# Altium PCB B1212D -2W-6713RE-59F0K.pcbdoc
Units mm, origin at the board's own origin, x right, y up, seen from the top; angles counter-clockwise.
Board outline 42 x 16 mm, 2 copper layers (Top Layer, Bottom Layer), stack 1.58 mm thick; 16 components, 10 nets, 42 pads, 75 vias.
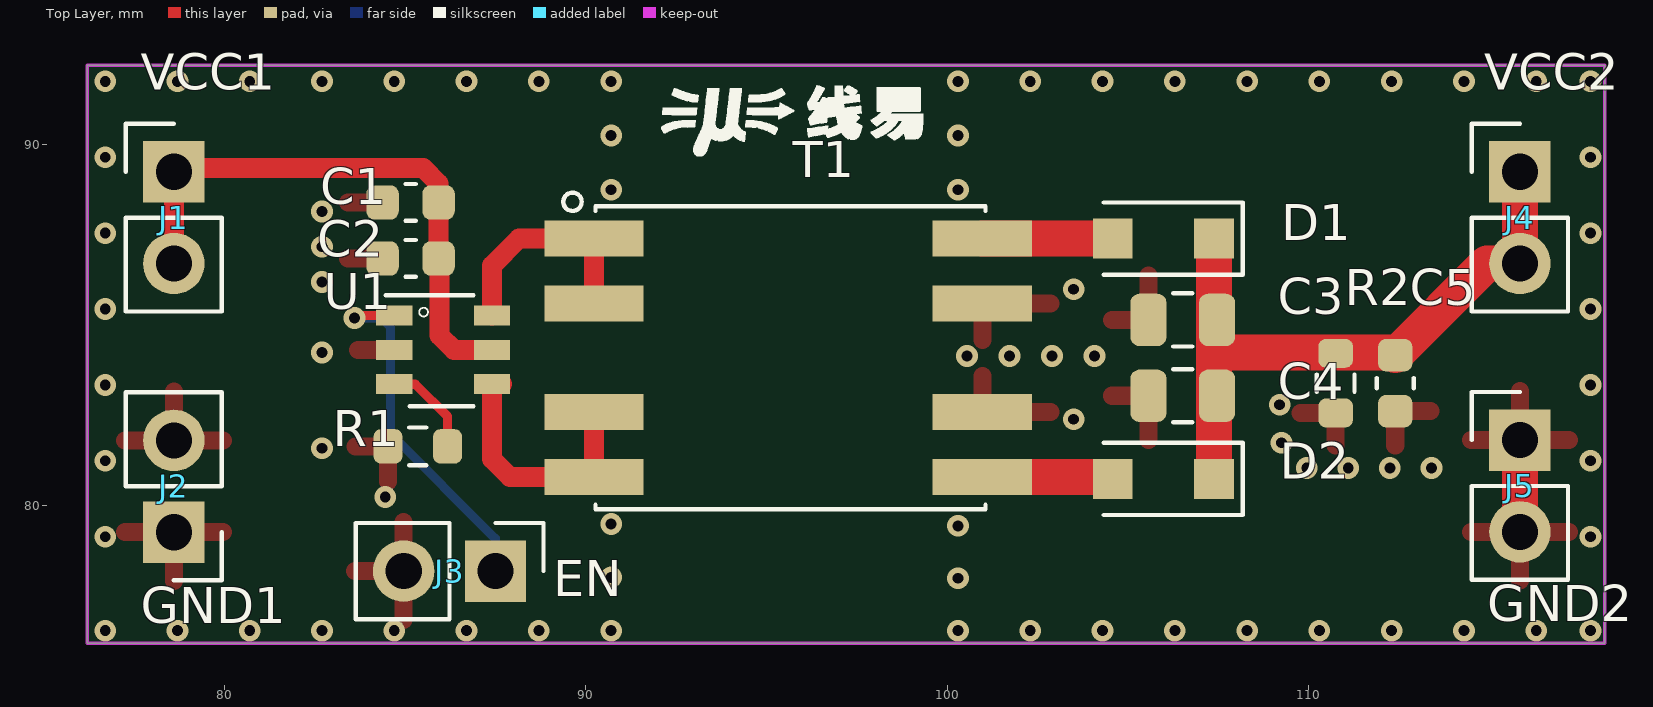
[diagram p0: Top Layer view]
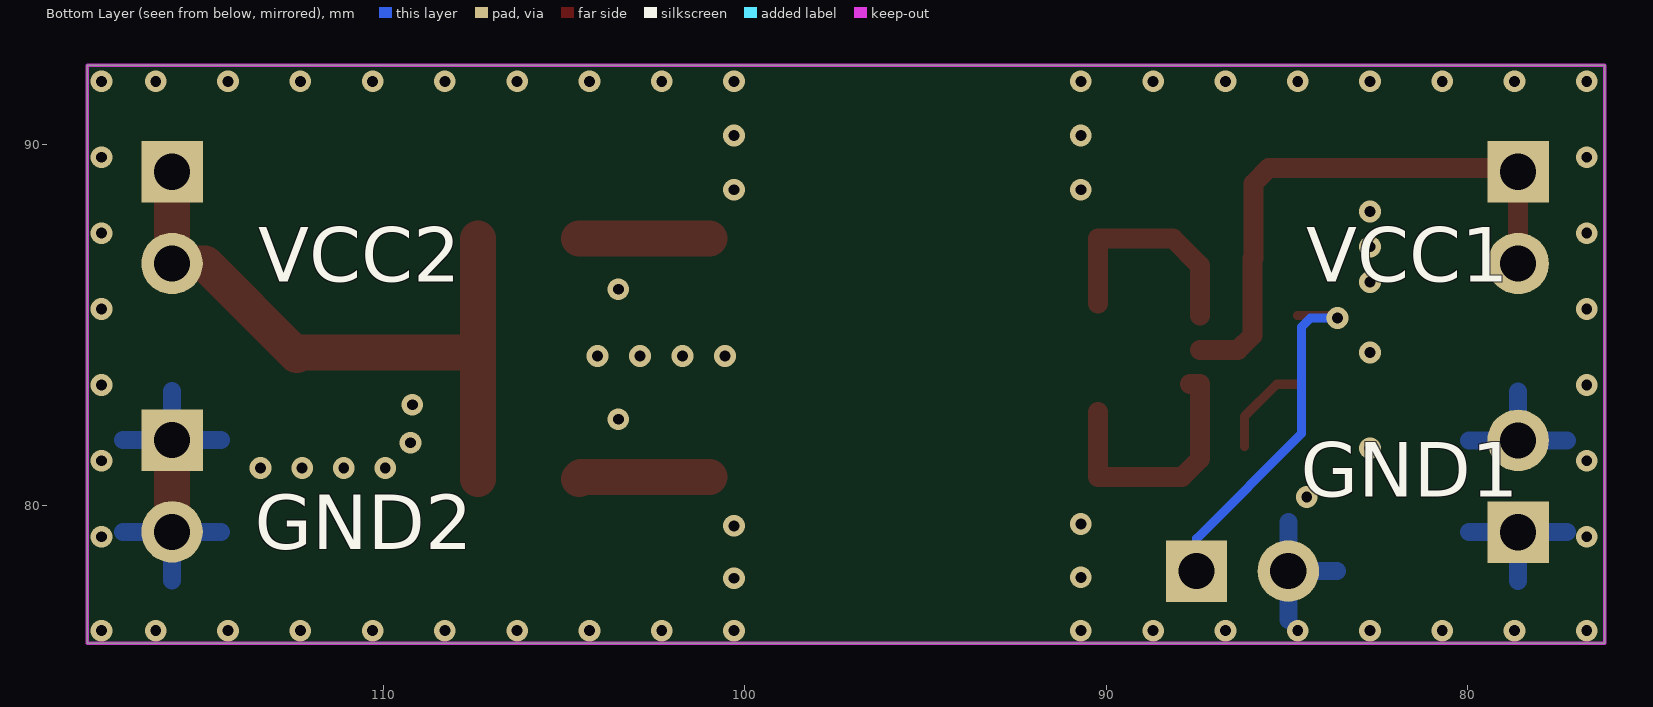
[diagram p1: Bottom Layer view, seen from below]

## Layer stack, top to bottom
Top Solder Mask Layer: solder mask 0.01, Dk 3.3
Top Layer: signal copper 0.035
Dielectric2: surface 1.51, FR4, Dk 4.5
Bottom Layer: signal copper 0.035
Bottom Solder Mask Layer: solder mask 0.01, Dk 3.3

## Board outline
76.2,92.2 118.2,92.2 118.2,76.2 76.2,76.2

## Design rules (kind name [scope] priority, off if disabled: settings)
BoardOutlineClearance copperThickness1oz [All] p0: genericclearance=0.254 ignorepadtopadclearanceinfootprint=FALSE except(0: Arc-SplitContinuation Track-SplitContinuation SMDPad-SplitContinuation THPad-SplitContinuation Via-SplitContinuation Fill-SplitContinuation Poly-SplitContinuation Region-SplitContinuation Text-SplitContinuation)
BoardOutlineClearance otherClearance [All] p0: genericclearance=0.254 ignorepadtopadclearanceinfootprint=FALSE except(0: Arc-SplitContinuation Track-SplitContinuation SMDPad-SplitContinuation THPad-SplitContinuation Via-SplitContinuation Fill-SplitContinuation Poly-SplitContinuation Region-SplitContinuation Text-SplitContinuation)
Clearance copperThickness1oz [All] p1: gap=0.178 ignorepadtopadclearanceinfootprint=FALSE
Clearance otherClearance [All] p1: gap=0.178 ignorepadtopadclearanceinfootprint=FALSE
DiffPairsRouting differentialPair [All] p1: maxuncoupledlength=10 minlimit=5 maxlimit=Infinity mostfreqgap=6 toplayer_minwidth=5 toplayer_prefwidth=100 toplayer_maxwidth=100 bottomlayer_minwidth=5 bottomlayer_prefwidth=100 bottomlayer_maxwidth=100
PasteMaskExpansion pasteMaskExpansion [All] p1: expansion=0
PlaneConnect innerPlane [All] p1: planeconnectstyle=Relief reliefexpansion=0.508 reliefentries=4 reliefconductorwidth=0.254 reliefairgap=0.254
PolygonConnect copper0 [All] p1: connectstyle=Relief reliefentries=4 reliefconductorwidth=19.685 polygonreliefangle="90 Angle" airgapwidth=19.685
RoutingVias viaSize [All] p1: viastyle="Through Hole" holewidth=24 minholewidth=11.811 maxholewidth=393.7 width=24 minwidth=11.811 maxwidth=393.7
SolderMaskExpansion solderMaskExpansion [IsVia] p1: useseparateexpansions=TRUE expansion=-1000 expansionbottom=-1000
SolderMaskExpansion solderMaskExpansion [All] p2: useseparateexpansions=TRUE expansion=2 expansionbottom=2
Width copperThickness1oz [All] p1: maxlimit=100 minlimit=5 preferedwidth=10

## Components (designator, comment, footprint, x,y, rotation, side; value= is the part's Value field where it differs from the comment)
C1 "10uF" C0603#1 85.15,88.4 r0 top
C2 "100nF" C0603#1 85.15,86.85 r0 top
C3 "10uF" C0603#2 106.518,85.15 r0 top
C4 "NC" coileasy:C_0805 106.518,83.05 r0 top
C5 "100nF" C0603#1 112.4,83.4 r90 top
D1 "B5819WS" SOD-323_L1.8-W1.3-LS2.5-RD 105.883,87.45 r180 top
D2 "B5819WS" SOD-323_L1.8-W1.3-LS2.5-RD 105.883,80.8 r180 top
J1 "HX PZ2.54-1x2P ZZ" HDR-TH_2P-P2.54-V-M-3 78.6,89.25 r0 top
J2 "HX PZ2.54-1x2P ZZ" HDR-TH_2P-P2.54-V-M-3 78.6,79.275 r180 top
J3 "HX PZ2.54-1x2P ZZ" HDR-TH_2P-P2.54-V-M-3 87.5,78.2 r270 top
J4 "HX PZ2.54-1x2P ZZ" HDR-TH_2P-P2.54-V-M-3 115.85,89.25 r0 top
J5 "HX PZ2.54-1x2P ZZ" HDR-TH_2P-P2.54-V-M-3 115.85,81.825 r0 top
R1 "R" coileasy:R_0603 85.35,81.65 r180 top
R2 "10kΩ" R0603 110.75,83.4 r270 top
T1 "CMT59F0K" "My Library:CMT59F0K" 95.6,84.1 r0 top
U1 "CMP6713RE" "My Library:SOT-23-6" 85.892,84.35 r0 top

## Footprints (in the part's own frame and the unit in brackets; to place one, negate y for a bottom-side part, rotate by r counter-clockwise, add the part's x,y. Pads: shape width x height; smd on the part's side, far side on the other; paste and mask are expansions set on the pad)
C0603#1 [mm]
  rrect50% 0.9x0.95 smd paste+0 mask+0: 1(-0.775,0) 2(0.775,0)
  silkscreen extent -0.14,-0.51 0.14,0.51
C0603#2 [mm]
  rrect50% 1x1.45 smd paste+0 mask+0: 1(-0.95,0) 2(0.95,0)
  silkscreen extent -0.26,-0.73 0.26,0.73
coileasy:C_0805 [mm]
  rrect50% 1x1.45 smd paste+0 mask+0: 1(-0.95,0) 2(0.95,0)
  silkscreen extent -0.26,-0.73 0.26,0.73
coileasy:R_0603 [mm]
  rrect50% 0.8x0.95 smd paste+0 mask+0: 1(-0.825,0) 2(0.825,0)
  silkscreen extent -0.24,-0.52 0.24,0.52
HDR-TH_2P-P2.54-V-M-3 [mm]
  rect 1.7x1.7 hole 1 paste+0 mask+0: 1(0,0)
  round 1.7 hole 1 paste+0 mask+0: 2(0,-2.54)
  silkscreen extent -1.33,-3.87 1.33,1.33
"My Library:CMT59F0K" [mm]
  rect 2.75x1 smd paste+0 mask+0: 1(-5.375,3.3) 2(-5.375,1.5) 3(-5.375,-1.5) 4(-5.375,-3.3) 5(5.375,-3.3) 6(5.375,-1.5) 7(5.375,1.5) 8(5.375,3.3)
  silkscreen extent -6.22,-4.19 5.46,4.57
"My Library:SOT-23-6" [mm]
  rect 1x0.55 smd paste+0 mask+0: 1(-1.192,0.921) 2(-1.192,-0.029) 3(-1.192,-0.979) 4(1.508,-0.979) 5(1.508,-0.029) 6(1.508,0.921)
  silkscreen extent -1.43,-1.59 1,1.48
R0603 [mm]
  rrect50% 0.8x0.95 smd paste+0 mask+0: 1(-0.825,0) 2(0.825,0)
  silkscreen extent -0.24,-0.52 0.24,0.52
SOD-323_L1.8-W1.3-LS2.5-RD [mm]
  rect 1.1x1.1 smd paste+0 mask+0: 1(-1.5,0.05) 2(1.3,0.05)
  silkscreen extent -2.3,-0.95 1.55,1.05

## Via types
v1: diameter 0.6, hole 0.3, Top Layer to Bottom Layer, 75 vias

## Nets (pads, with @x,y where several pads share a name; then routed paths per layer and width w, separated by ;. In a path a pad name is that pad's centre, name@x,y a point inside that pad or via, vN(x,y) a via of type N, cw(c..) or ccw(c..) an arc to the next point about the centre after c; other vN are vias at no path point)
$1N7: J3.1 U1.1 | length 10.3
  Top Layer w0.25: U1.1 83.721,85.271 v1@83.65,85.2 ; v1@83.65,85.2 v1(83.6,85.2) 83.6,85.15 v1@83.65,85.2
  Bottom Layer w0.25: v1(83.6,85.2) 84.35,85.2 84.6,84.95 84.6,82 87.5,79.1 J3.1
$1N10: R1.1 U1.3 | length 2.7
  Top Layer w0.254: U1.3 85.279,83.371 86.175,82.475 R1.1
D1: D1.2 T1.8 | length 3.6
  Top Layer w1: T1.8 D1.2
D2: D2.2 T1.5 | length 3.6
  Top Layer w1: T1.5 104.533,80.8 D2.2
GND1: C1.1 C2.1 J2.1 J2.2 J3.2 R1.2 U1.2
  other v1: 76.7,76.55 78.7,76.55 80.7,76.55 82.7,76.55 84.7,76.55 86.7,76.55 88.7,76.55 90.7,76.55 90.7,78.025 76.7,79.15 90.7,79.5 84.45,80.25 76.7,81.25 82.7,81.6 76.7,83.35 82.7,84.25 76.7,85.45 82.7,86.2 82.7,87.175 76.7,87.55 82.7,88.15 90.7,88.75 76.7,89.65 90.7,90.25 76.7,91.75 78.7,91.75 80.7,91.75 82.7,91.75 84.7,91.75 86.7,91.75 88.7,91.75 90.7,91.75
GND2: C3.1 C4.1 C5.1 J5.1 J5.2 R2.2 T1.6 T1.7 | length 2.5
  Top Layer w1: J5.2 J5.1
  other v1: 100.3,76.55 102.3,76.55 104.3,76.55 106.3,76.55 108.3,76.55 110.3,76.55 112.3,76.55 114.3,76.55 116.3,76.55 117.8,76.55 100.3,78 117.8,79.15 100.3,79.45 109.95,81.05 111.1,81.05 112.25,81.05 113.4,81.05 117.8,81.25 109.25,81.75 103.5,82.4 109.2,82.8 117.8,83.35 100.55,84.15 101.725,84.15 102.9,84.15 104.075,84.15 117.8,85.45 103.5,86 117.8,87.55 100.3,88.75 117.8,89.65 100.3,90.25 100.3,91.75 102.3,91.75 104.3,91.75 106.3,91.75 108.3,91.75 110.3,91.75 112.3,91.75 114.3,91.75 116.3,91.75 117.8,91.75
VCC1: C1.2 C2.2 J1.1 J1.2 U1.5 | length 16.1
  Top Layer w0.55: J1.2 J1.1 J1.1@78.7,89.35 ; J1.1@78.85,89.5 J1.1@78.7,89.35 ; C2.2 C1.2 85.925,88.925 85.5,89.35 J1.1@78.7,89.35 ; C2.2@85.95,86.85 85.95,84.721 86.35,84.321 U1.5
VCC2: C3.2 C4.2 C5.2 D1.1 D2.1 J4.1 J4.2 R2.1 | length 18.6
  Top Layer w1: D2.1 D1.1 ; 107.45,84.25 C5.2@112.325,84.25 ; C5.2 114.935,86.71 J4.2 J4.1
VD1: T1.1 T1.2 U1.6 | length 6.3
  Top Layer w0.55: U1.6 87.4,86.65 88.15,87.4 T1.1 T1.2
VD2: T1.3 T1.4 U1.4 | length 7.2
  Top Layer w0.55: U1.4@87.679,83.371 U1.4 87.4,81.3 87.9,80.8 T1.4 T1.3

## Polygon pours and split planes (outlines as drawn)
GND2 on Top Layer (solid, remove dead copper, pour order 2): 118.2,92.2 118.2,76.2 99.6,76.2 99.6,92.2
GND2 on Bottom Layer (solid, remove dead copper, pour order 8): 118.2,92.2 118.2,76.2 99.6,76.2 99.6,92.2
GND1 on Top Layer (solid, remove dead copper, pour order 6): 76.2,92.2 91.6,92.2 91.55,76.2 76.2,76.2
GND1 on Bottom Layer (solid, remove dead copper, pour order 12): 76.2,92.2 91.6,92.2 91.55,76.2 76.2,76.2

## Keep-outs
Board Outline Layer:
  the board outline again, w0.1

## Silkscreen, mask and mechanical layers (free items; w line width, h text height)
Top Silkscreen Layer:
  drawing of 9 lines, arcs and shapes, not listed
  text "VCC1" at 77.689,91.512 h1
  text "VCC2" at 114.859,91.512 h1
  text "EN" at 89.1,77.5 h1
  text "GND2" at 114.943,76.804 h1
  text "GND1" at 77.689,76.754 h1
Bottom Silkscreen Layer:
  text "VCC1" at 84.461,86.2 h1.5
  text "VCC2" at 113.458,86.2 h1.5
  text "GND1" at 84.611,80.25 h1.5
  text "GND2" at 113.558,78.8 h1.5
